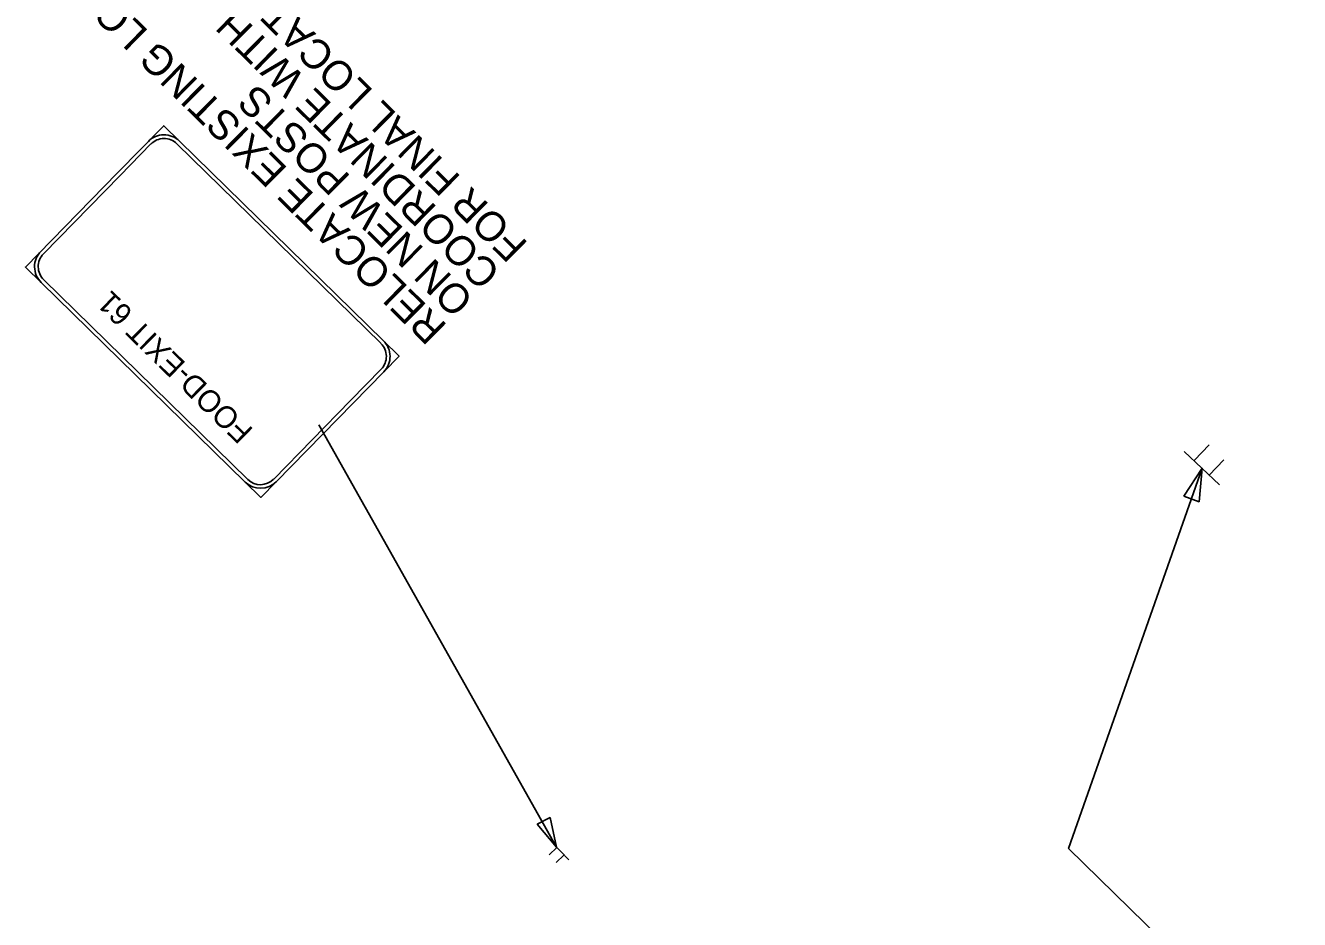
# Model space of a CAD drawing. Extents: x -5665 to 1997148, y 4 to 812485.
# Drawn here: x 1961807 to 1962885, y 798884 to 799640 of the extents above; entities that cross this region are included whole.
import ezdxf

# ---------------------------------------------------------------- set-up
doc = ezdxf.new("R2010")
doc.units = 0
for name, color, linetype in [('RD_EX_Misc', 7, 'Continuous'), ('RD_PD_Final_TX', 7, 'Continuous'), ('RD_SHT_TX', 7, 'Continuous')]:
    doc.layers.add(name, color=color, linetype=linetype)

msp = doc.modelspace()

# ---------------------------------------------------------------- linework, layer by layer
at = {"layer": 'RD_EX_Misc'}
msp.add_line((1962256.6, 798945.1), (1962055.2, 799302.5), dxfattribs=at)
at = {"layer": 'RD_PD_Final_TX'}
for points in [[(1962787.4, 799242), (1962800.4, 799237.4), (1962803.1, 799265.7)], [(1962240, 798964.6), (1962251.1, 798970.1), (1962256.6, 798945.1)]]:
    msp.add_lwpolyline(points, close=True, dxfattribs=at)
at = {"layer": 'RD_SHT_TX'}
for p, q in [((1962787.7, 799279.8), (1962817.6, 799251.7)), ((1962808.8, 799285.4), (1962796.6, 799272.4)), ((1962821.2, 799272.8), (1962808.9, 799259.9)), ((1962250.4, 798938.7), (1962256.9, 798944.8)), ((1962266.9, 798934.3), (1962252.8, 798949.1)), ((1962256.3, 798932.1), (1962262.7, 798938.2))]:
    msp.add_line(p, q, dxfattribs=at)
for points in [[(1962123.3, 799360.6), (1961924, 799555.5), (1961885, 799515.7)], [(1961913.2, 799540.1), (1961887.2, 799513.5)], [(1962107.8, 799371.4), (1961935.1, 799540.3)], [(1961885, 799515.7), (1961807, 799435.9), (1962006.3, 799241), (1962084.3, 799320.7), (1962084.3, 799320.7)], [(1961887.2, 799513.5), (1961822.2, 799447)], [(1961822.5, 799425.1), (1961995.2, 799256.2)], [(1962084.3, 799320.7), (1962123.3, 799360.6), (1962123.3, 799360.6)], [(1962082.1, 799322.9), (1962108.1, 799349.5)], [(1962017.1, 799256.4), (1962082.1, 799322.9)], [(1962084.3, 799320.7), (1962019.3, 799254.3)], [(1963352.9, 798295.6), (1962689.9, 798944), (1962803.1, 799265.7)]]:
    msp.add_lwpolyline(points, dxfattribs=at)
for centre, radius, start, end in [((1961924.3, 799529.2), 18.6, 45.6377, 135.6379), ((1961924.3, 799529.2), 15.5, 45.6377, 135.6379), ((1961833.3, 799436.2), 18.6, 135.6376, 225.6379), ((1961833.3, 799436.2), 15.5, 135.6376, 225.6379), ((1962097, 799360.3), 15.5, 315.6375, 45.6377), ((1962097, 799360.3), 18.6, 315.6375, 45.6377), ((1962006, 799267.3), 18.6, 225.6379, 315.6375), ((1962006, 799267.3), 15.5, 225.6379, 315.6375)]:
    msp.add_arc(centre, radius, start, end, dxfattribs=at)

# ---------------------------------------------------------------- texts
for s, height, rotation, p in [('COORDINATE WITH SCDOT', 25, 135.4569, (1962210.4, 799432.7)), ('FOR FINAL LOCATION ', 25, 135.4569, (1962233.3, 799455.9)), ('RELOCATE EXISTING LOGO', 25, 135.4569, (1962164.8, 799386.3)), ('ON NEW POSTS', 25, 135.4569, (1962187.6, 799409.5)), ('FOOD-EXIT 61', 18.587, 135.6376, (1962000.7, 799298.3))]:
    msp.add_text(s, height=height, rotation=rotation, dxfattribs=at).set_placement(p)

doc.saveas('drawing.dxf')
